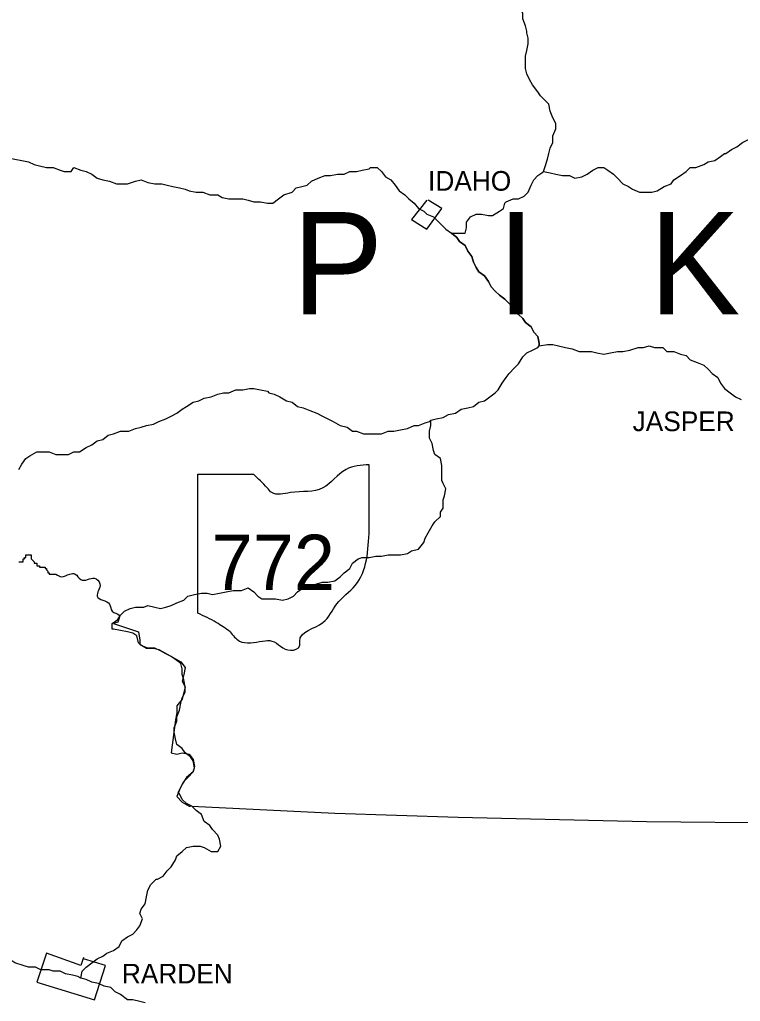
# Model space of a CAD drawing. Extents: x 0 to 34, y 0 to 22.
# Drawn here: x 5.134 to 5.85, y 17.302 to 18.276 of the extents above; entities that cross this region are included whole.
import ezdxf

# ---------------------------------------------------------------- set-up
doc = ezdxf.new("R2010")
doc.units = 0
doc.layers.add('Default', color=7, linetype='Continuous')
doc.layers.add('TR_Turning_Path1', color=7, linetype='Continuous')

msp = doc.modelspace()

# ---------------------------------------------------------------- linework, layer by layer
at = {"layer": 'Default'}
msp.add_line((5.23183, 17.67809), (5.22774, 17.67673), dxfattribs=at)
for points in [[(5.63813, 18.26437), (5.63677, 18.26982), (5.63404, 18.27664), (5.63404, 18.28209), (5.63132, 18.28891), (5.62995, 18.29436), (5.62995, 18.30118), (5.62723, 18.30663), (5.62586, 18.31345), (5.62586, 18.3189), (5.62314, 18.32572), (5.62177, 18.33254), (5.62041, 18.33935), (5.62041, 18.34344), (5.62041, 18.35026), (5.62041, 18.35162)], [(5.65449, 18.1253), (5.65586, 18.12939), (5.65858, 18.13757), (5.65995, 18.14302), (5.66131, 18.14848), (5.66404, 18.15393), (5.66404, 18.16075), (5.66677, 18.16756), (5.66677, 18.17302), (5.66404, 18.17847), (5.66131, 18.18529), (5.65995, 18.1921), (5.65586, 18.19619), (5.65177, 18.20029), (5.64904, 18.20438), (5.64359, 18.21119), (5.64086, 18.21665), (5.63813, 18.2221), (5.63677, 18.22755), (5.63677, 18.23301), (5.63677, 18.23982), (5.63813, 18.24528), (5.6395, 18.25209), (5.6395, 18.25755), (5.63813, 18.263), (5.63813, 18.263), (5.63813, 18.26437)], [(5.83583, 18.14302), (5.84128, 18.14711), (5.84674, 18.14984), (5.85219, 18.15393), (5.85764, 18.15666), (5.8631, 18.15802), (5.86991, 18.15802), (5.87537, 18.15802), (5.88082, 18.15529), (5.88764, 18.15393), (5.89309, 18.15529), (5.89582, 18.15666)], [(5.65449, 18.1253), (5.66131, 18.12393), (5.66677, 18.12257), (5.67358, 18.12121), (5.6804, 18.12121), (5.68585, 18.11848), (5.69267, 18.11984), (5.69812, 18.12257), (5.70358, 18.12666), (5.70903, 18.12939), (5.71448, 18.12939), (5.71858, 18.12666), (5.72403, 18.12257), (5.72812, 18.11848), (5.73357, 18.11303), (5.73903, 18.1103), (5.74312, 18.10757), (5.74993, 18.10485), (5.75675, 18.10485), (5.7622, 18.10485), (5.76766, 18.10621), (5.77448, 18.1103), (5.78129, 18.11303), (5.78402, 18.11712), (5.79084, 18.12121), (5.79629, 18.1253), (5.80038, 18.12939), (5.80583, 18.12939), (5.81401, 18.13211), (5.8181, 18.13484), (5.82492, 18.1362), (5.83038, 18.14029), (5.83447, 18.14302), (5.83583, 18.14302), (5.83583, 18.14302)], [(5.0655, 18.10212), (5.07231, 18.10212), (5.0764, 18.10621), (5.08049, 18.1103), (5.08731, 18.11303), (5.0914, 18.11848), (5.09686, 18.12257), (5.10231, 18.12666), (5.1064, 18.13075), (5.11049, 18.13484), (5.11731, 18.13757), (5.12276, 18.13893), (5.12958, 18.13757), (5.13639, 18.1362), (5.14321, 18.13484), (5.14867, 18.13211), (5.15412, 18.13075), (5.16094, 18.12939), (5.16775, 18.12939), (5.17457, 18.12666), (5.17866, 18.1253), (5.18548, 18.1253), (5.18548, 18.1253)], [(5.18548, 18.1253), (5.1882, 18.12939), (5.19502, 18.12666), (5.20048, 18.1253), (5.20593, 18.12257), (5.21138, 18.11848), (5.21684, 18.11712), (5.22365, 18.11575), (5.23047, 18.11303), (5.23592, 18.11303), (5.24138, 18.11303), (5.24956, 18.11575), (5.25501, 18.11712), (5.26183, 18.11439), (5.26865, 18.11303), (5.27546, 18.11303), (5.28092, 18.11166), (5.28637, 18.1103), (5.29319, 18.10894), (5.29864, 18.10757), (5.30273, 18.10621), (5.30273, 18.10621)], [(5.30273, 18.10621), (5.30955, 18.10485), (5.31637, 18.10485), (5.32318, 18.10212), (5.33136, 18.10212), (5.33545, 18.09939), (5.34227, 18.09803), (5.34909, 18.09803), (5.35591, 18.09803), (5.36136, 18.09667), (5.36681, 18.0953), (5.37363, 18.0953), (5.38045, 18.09394), (5.3859, 18.09394), (5.39135, 18.09803), (5.39681, 18.10212), (5.40499, 18.10485), (5.40908, 18.10894), (5.41453, 18.1103), (5.41999, 18.11166), (5.42408, 18.11575), (5.43089, 18.11848), (5.43771, 18.12121), (5.44316, 18.12121), (5.44998, 18.12257), (5.4568, 18.12257), (5.46225, 18.1253), (5.46907, 18.1253), (5.47452, 18.12666), (5.48134, 18.12802), (5.4827, 18.12939)], [(5.4827, 18.12939), (5.48952, 18.12939), (5.49361, 18.1253), (5.4977, 18.11984), (5.50315, 18.11712), (5.50724, 18.11166), (5.51134, 18.10621), (5.51679, 18.10212), (5.52088, 18.09803), (5.52633, 18.09394), (5.53042, 18.08848), (5.53588, 18.08576), (5.5386, 18.08303), (5.54542, 18.0803), (5.54815, 18.07758), (5.5536, 18.07212), (5.55769, 18.06803), (5.56315, 18.06394), (5.56315, 18.06394), (5.56315, 18.06394)], [(5.61768, 18.0953), (5.6245, 18.09803), (5.62995, 18.09803), (5.63541, 18.10076), (5.6395, 18.10485), (5.64222, 18.11166), (5.64495, 18.11712), (5.64904, 18.12121), (5.65313, 18.12393), (5.65449, 18.1253)], [(5.5386, 18.09667), (5.52361, 18.07758), (5.5386, 18.06803), (5.5536, 18.08848), (5.53997, 18.09667)], [(5.56315, 18.06394), (5.56996, 18.06394), (5.57678, 18.06394), (5.57814, 18.0694), (5.57814, 18.07485), (5.58223, 18.0803), (5.58769, 18.08303), (5.59314, 18.08303), (5.59996, 18.08167), (5.60405, 18.08167), (5.61086, 18.08576), (5.61496, 18.08848), (5.61632, 18.09394), (5.61632, 18.09394), (5.61768, 18.0953)], [(5.6504, 17.95214), (5.6504, 17.95351), (5.6504, 17.95487), (5.64904, 17.96169), (5.64495, 17.96578), (5.64222, 17.97123), (5.63677, 17.97532), (5.63404, 17.97941), (5.62995, 17.9835), (5.62586, 17.98895), (5.62041, 17.99441), (5.61632, 17.9985), (5.61086, 18.00259), (5.60677, 18.00668), (5.60268, 18.01077), (5.59996, 18.01622), (5.59587, 18.02168), (5.59041, 18.02577), (5.58769, 18.02986), (5.58496, 18.03531), (5.5836, 18.04076), (5.57951, 18.04622), (5.57678, 18.05167), (5.57133, 18.05576), (5.5686, 18.05985), (5.56315, 18.06394)], [(5.56315, 18.06394), (5.5686, 18.05985), (5.57133, 18.05576), (5.57678, 18.05167), (5.57951, 18.04622), (5.5836, 18.04076), (5.58496, 18.03531), (5.58769, 18.02986), (5.59041, 18.02577), (5.59587, 18.02168), (5.59996, 18.01622), (5.60268, 18.01077), (5.60677, 18.00668), (5.61086, 18.00259), (5.61632, 17.9985), (5.62041, 17.99441), (5.62586, 17.98895), (5.62995, 17.9835), (5.63404, 17.97941), (5.63677, 17.97532), (5.64222, 17.97123), (5.64495, 17.96578), (5.64904, 17.96169), (5.6504, 17.95487), (5.6504, 17.95351), (5.6504, 17.95214)], [(5.54269, 17.87852), (5.54815, 17.87988), (5.55496, 17.88124), (5.56042, 17.88397), (5.56724, 17.88533), (5.57269, 17.88943), (5.57951, 17.89079), (5.58496, 17.89215), (5.59041, 17.89624), (5.59587, 17.89761), (5.60132, 17.9017), (5.60677, 17.90579), (5.6095, 17.90851), (5.61359, 17.91533), (5.61768, 17.92078), (5.62041, 17.92487), (5.62586, 17.93033), (5.62995, 17.93442), (5.63404, 17.94124), (5.63813, 17.94533), (5.64359, 17.94805), (5.64904, 17.95078), (5.6504, 17.95214), (5.6504, 17.95214)], [(5.54269, 17.87852), (5.54815, 17.87988), (5.55496, 17.88124), (5.56042, 17.88397), (5.56724, 17.88533), (5.57269, 17.88943), (5.57951, 17.89079), (5.58496, 17.89215), (5.59041, 17.89624), (5.59587, 17.89761), (5.60132, 17.9017), (5.60677, 17.90579), (5.6095, 17.90851), (5.61359, 17.91533), (5.61768, 17.92078), (5.62041, 17.92487), (5.62586, 17.93033), (5.62995, 17.93442), (5.63404, 17.94124), (5.63813, 17.94533), (5.64359, 17.94805), (5.64904, 17.95078), (5.6504, 17.95214), (5.6504, 17.95214)], [(5.6504, 17.95214), (5.65858, 17.95351), (5.66404, 17.95351), (5.66949, 17.95214), (5.67631, 17.95078), (5.68313, 17.94942), (5.68994, 17.94669), (5.6954, 17.94669), (5.70221, 17.94669), (5.70767, 17.94533), (5.71448, 17.94396), (5.7213, 17.94533), (5.72812, 17.94669), (5.73357, 17.94669), (5.74039, 17.94805), (5.74857, 17.95078), (5.75402, 17.95078), (5.75948, 17.95214), (5.76493, 17.95078), (5.77311, 17.95078), (5.7772, 17.94669), (5.78402, 17.94669), (5.79084, 17.94396), (5.79629, 17.9426), (5.80038, 17.93851), (5.8072, 17.93578), (5.81401, 17.93305), (5.8181, 17.92896), (5.8222, 17.92487), (5.82765, 17.92078), (5.83038, 17.91533), (5.83447, 17.90988), (5.83992, 17.90579), (5.84537, 17.9017), (5.85083, 17.89897)], [(5.6504, 17.95214), (5.65858, 17.95351), (5.66404, 17.95351), (5.66949, 17.95214), (5.67631, 17.95078), (5.68313, 17.94942), (5.68994, 17.94669), (5.6954, 17.94669), (5.70221, 17.94669), (5.70767, 17.94533), (5.71448, 17.94396), (5.7213, 17.94533), (5.72812, 17.94669), (5.73357, 17.94669), (5.74039, 17.94805), (5.74857, 17.95078), (5.75402, 17.95078), (5.75948, 17.95214), (5.76493, 17.95078), (5.77311, 17.95078), (5.7772, 17.94669), (5.78402, 17.94669), (5.79084, 17.94396), (5.79629, 17.9426), (5.80038, 17.93851), (5.8072, 17.93578), (5.81401, 17.93305), (5.8181, 17.92896), (5.8222, 17.92487), (5.82765, 17.92078), (5.83038, 17.91533), (5.83447, 17.90988), (5.83992, 17.90579), (5.84537, 17.9017), (5.85083, 17.89897)], [(5.23592, 17.86761), (5.24274, 17.86761), (5.24956, 17.87034), (5.25501, 17.8717), (5.26047, 17.87306), (5.26728, 17.87443), (5.27274, 17.87715), (5.27955, 17.87988), (5.28501, 17.88261), (5.29046, 17.88533), (5.29591, 17.88943), (5.3, 17.89215), (5.30682, 17.89624), (5.31228, 17.89761), (5.31773, 17.90033), (5.32455, 17.9017), (5.33136, 17.90442), (5.33682, 17.90579), (5.34227, 17.90579), (5.34909, 17.90851), (5.35591, 17.90851), (5.36272, 17.90988), (5.36681, 17.90988), (5.37363, 17.90851), (5.38045, 17.90715), (5.38181, 17.90579), (5.38181, 17.90579)], [(5.38181, 17.90579), (5.38726, 17.90442), (5.39272, 17.9017), (5.39953, 17.89761), (5.40499, 17.89624), (5.41044, 17.89215), (5.4159, 17.89079), (5.42271, 17.88806), (5.42953, 17.88533), (5.43498, 17.88261), (5.44044, 17.87988), (5.44589, 17.87715), (5.45271, 17.87306), (5.45953, 17.8717), (5.46498, 17.86761), (5.46907, 17.86761), (5.47589, 17.86488), (5.48134, 17.86488), (5.48816, 17.86488), (5.49361, 17.86488), (5.50043, 17.86761), (5.50588, 17.86761), (5.5127, 17.86897), (5.51952, 17.87034), (5.52633, 17.87306), (5.53042, 17.87306), (5.53724, 17.87579), (5.54133, 17.87715), (5.54269, 17.87852)], [(5.55224, 17.78717), (5.55496, 17.79126), (5.55496, 17.79944), (5.55633, 17.80353), (5.55769, 17.81035), (5.55496, 17.8158), (5.5536, 17.81853), (5.5536, 17.82671), (5.5536, 17.83352), (5.55224, 17.84034), (5.54678, 17.84443), (5.54542, 17.84852), (5.54406, 17.85534), (5.54133, 17.86079), (5.54133, 17.86761), (5.54269, 17.87306), (5.54269, 17.87715), (5.54269, 17.87852)], [(5.13367, 17.82943), (5.13639, 17.83489), (5.14048, 17.84034), (5.14458, 17.84307), (5.15139, 17.84716), (5.15685, 17.84716), (5.16366, 17.84716), (5.17048, 17.84443), (5.17593, 17.84443), (5.18275, 17.84443), (5.1882, 17.84716), (5.19366, 17.84716), (5.20048, 17.85125), (5.20593, 17.85398), (5.21138, 17.85807), (5.21684, 17.85943), (5.22229, 17.86352), (5.22774, 17.86488), (5.23456, 17.86761), (5.23592, 17.86761), (5.23592, 17.86761)], [(5.48151, 17.76978), (5.48151, 17.83421)], [(5.31125, 17.68696), (5.31125, 17.825), (5.36647, 17.825)], [(5.49361, 17.74354), (5.50043, 17.7449), (5.50588, 17.7449), (5.5127, 17.7449), (5.51952, 17.74627), (5.52361, 17.74899), (5.53042, 17.75036), (5.53588, 17.75717), (5.53724, 17.76126), (5.53997, 17.76672), (5.54406, 17.77353), (5.54678, 17.77762), (5.55224, 17.78308), (5.55224, 17.78581), (5.55224, 17.78717)], [(5.13367, 17.73809), (5.13503, 17.73809), (5.13503, 17.73809), (5.13503, 17.73809), (5.13503, 17.73809), (5.13503, 17.73809), (5.13639, 17.73809), (5.13639, 17.73809), (5.13639, 17.73809), (5.13639, 17.73809), (5.13776, 17.73809), (5.13776, 17.73809), (5.13776, 17.73809), (5.13776, 17.73809), (5.13776, 17.73809), (5.13776, 17.73809), (5.13776, 17.73809), (5.13776, 17.73809), (5.13776, 17.73809), (5.13776, 17.73945), (5.13776, 17.74081), (5.13912, 17.74081), (5.13912, 17.74081), (5.13912, 17.74081), (5.13912, 17.74218), (5.14048, 17.74218), (5.14048, 17.74218), (5.14048, 17.74218), (5.14048, 17.74218), (5.14048, 17.74218), (5.14048, 17.74218), (5.14048, 17.74354), (5.14048, 17.74354), (5.14048, 17.74354), (5.14048, 17.74354), (5.14048, 17.74354), (5.14048, 17.74354), (5.14048, 17.74354), (5.14048, 17.7449), (5.14048, 17.7449), (5.14185, 17.7449), (5.14185, 17.7449), (5.14185, 17.7449), (5.14185, 17.7449), (5.14185, 17.7449), (5.14321, 17.7449), (5.14321, 17.7449), (5.14321, 17.7449), (5.14321, 17.7449), (5.14321, 17.7449), (5.14321, 17.7449), (5.14321, 17.7449), (5.14321, 17.7449), (5.14321, 17.7449)], [(5.14321, 17.7449), (5.14321, 17.7449), (5.14321, 17.7449), (5.14458, 17.7449), (5.14458, 17.7449), (5.14458, 17.7449), (5.14594, 17.7449), (5.14594, 17.7449), (5.14594, 17.74354), (5.14594, 17.74354), (5.14594, 17.74354), (5.14594, 17.74354), (5.14594, 17.74354), (5.14594, 17.74218), (5.14594, 17.74218), (5.14594, 17.74218), (5.14594, 17.74218), (5.14594, 17.74218), (5.14594, 17.74218), (5.14594, 17.74218), (5.14594, 17.74081), (5.14594, 17.74081), (5.14594, 17.74081), (5.14594, 17.74081), (5.14594, 17.74081), (5.1473, 17.73945), (5.1473, 17.73945), (5.14867, 17.73809), (5.14867, 17.73809), (5.14867, 17.73809), (5.14867, 17.73809), (5.14867, 17.73809), (5.14867, 17.73809), (5.14867, 17.73672), (5.14867, 17.73672), (5.14867, 17.73672), (5.14867, 17.73672), (5.15003, 17.73672), (5.15003, 17.73672), (5.15139, 17.73672), (5.15139, 17.73672), (5.15139, 17.73672), (5.15139, 17.73672), (5.15139, 17.73672), (5.15139, 17.73536), (5.15139, 17.73536), (5.15139, 17.734), (5.15276, 17.734), (5.15276, 17.734), (5.15276, 17.734), (5.15276, 17.734), (5.15412, 17.734), (5.15412, 17.734), (5.15412, 17.73263), (5.15412, 17.73263), (5.15548, 17.73263), (5.15548, 17.73263), (5.15548, 17.73263), (5.15548, 17.73263), (5.15685, 17.73263), (5.15685, 17.73263), (5.15821, 17.73263), (5.15821, 17.73263), (5.15821, 17.73263), (5.15821, 17.73263), (5.15957, 17.73263), (5.15957, 17.73263), (5.15957, 17.73263), (5.15957, 17.73263), (5.15957, 17.73263), (5.15957, 17.73127), (5.15957, 17.73127), (5.16094, 17.73127), (5.16094, 17.73127), (5.16094, 17.7299), (5.16094, 17.7299), (5.16094, 17.7299), (5.16094, 17.7299), (5.16094, 17.7299), (5.16094, 17.7299), (5.16094, 17.7299), (5.16094, 17.7299), (5.1623, 17.72854), (5.1623, 17.72854), (5.1623, 17.72854), (5.1623, 17.72854), (5.1623, 17.72854), (5.1623, 17.72718), (5.16366, 17.72718), (5.16366, 17.72581), (5.16503, 17.72581), (5.16503, 17.72581), (5.16503, 17.72581), (5.16503, 17.72581), (5.16503, 17.72581), (5.16503, 17.72581), (5.16503, 17.72581), (5.16503, 17.72581), (5.16639, 17.72581), (5.16775, 17.72581), (5.16775, 17.72581)], [(5.35454, 17.70945), (5.36136, 17.71218), (5.36681, 17.70809), (5.3709, 17.704), (5.37499, 17.70127), (5.38181, 17.70127), (5.38863, 17.70127), (5.39544, 17.69991), (5.4009, 17.70127), (5.40635, 17.704), (5.41044, 17.70809), (5.4159, 17.71218), (5.42271, 17.71354), (5.42953, 17.71627), (5.43498, 17.71763), (5.44044, 17.71763), (5.44725, 17.719), (5.45271, 17.72309), (5.4568, 17.72718), (5.46225, 17.73127), (5.46498, 17.73672), (5.47043, 17.74081), (5.47452, 17.74218), (5.48134, 17.74218), (5.48816, 17.74354), (5.49225, 17.74354), (5.49361, 17.74354)], [(5.16775, 17.72581), (5.16775, 17.72581), (5.16775, 17.72581), (5.16775, 17.72581), (5.16775, 17.72581), (5.16775, 17.72581), (5.16912, 17.72581), (5.16912, 17.72581), (5.16912, 17.72581), (5.16912, 17.72581), (5.16912, 17.72581), (5.16912, 17.72581), (5.16912, 17.72581), (5.17048, 17.72581), (5.17048, 17.72581), (5.17048, 17.72581), (5.17048, 17.72581)], [(5.23456, 17.68491), (5.23865, 17.689), (5.2441, 17.69173), (5.24956, 17.69309), (5.25774, 17.69309), (5.26183, 17.69446), (5.26865, 17.69309), (5.2741, 17.69173), (5.27955, 17.69309), (5.28501, 17.69446), (5.29046, 17.69718), (5.29728, 17.69991), (5.30137, 17.704), (5.30819, 17.70536), (5.315, 17.70673), (5.32046, 17.70673), (5.32591, 17.70536), (5.33273, 17.70673), (5.33954, 17.70809), (5.34636, 17.70945), (5.35318, 17.70945), (5.35454, 17.70945)], [(5.22638, 17.67128), (5.22638, 17.67673), (5.23183, 17.68082), (5.23456, 17.68491)], [(5.22774, 17.67673), (5.25229, 17.66855), (5.25365, 17.66037), (5.25365, 17.65628), (5.26047, 17.65219), (5.26728, 17.65219), (5.27274, 17.65083), (5.29455, 17.63856), (5.29864, 17.6331), (5.29728, 17.62628), (5.29591, 17.61947), (5.29864, 17.61401), (5.29591, 17.60174), (5.29046, 17.59493), (5.29046, 17.58811), (5.2891, 17.58129), (5.28501, 17.54857), (5.29046, 17.54721), (5.29591, 17.54857), (5.30273, 17.54721), (5.30682, 17.54175), (5.30819, 17.53494), (5.30682, 17.52948), (5.3, 17.52403), (5.29591, 17.51721), (5.29319, 17.51176), (5.29046, 17.50494), (5.29591, 17.49949), (5.30273, 17.4954), (5.3041, 17.4954)], [(5.29046, 17.58402), (5.29319, 17.59084), (5.29455, 17.59765), (5.29591, 17.60311), (5.29864, 17.60856), (5.29864, 17.61401), (5.29728, 17.62083), (5.29591, 17.62628), (5.29591, 17.63174), (5.29455, 17.63719), (5.29046, 17.63992), (5.28501, 17.64401), (5.27955, 17.64674), (5.2741, 17.64946), (5.26865, 17.65219), (5.26183, 17.65219), (5.25501, 17.65492), (5.25229, 17.65764), (5.25092, 17.66446), (5.24683, 17.66719), (5.24138, 17.66855), (5.23456, 17.66991), (5.22774, 17.67128), (5.22638, 17.67128), (5.22638, 17.67128)], [(5.29182, 17.50903), (5.29455, 17.51448), (5.29728, 17.51994), (5.30137, 17.52403), (5.30682, 17.52948), (5.30819, 17.53357), (5.30682, 17.54039), (5.3041, 17.54448), (5.29864, 17.54857), (5.29591, 17.55266), (5.29046, 17.55675), (5.2891, 17.5622), (5.28773, 17.56902), (5.28773, 17.57311), (5.29046, 17.57993), (5.29046, 17.58402), (5.29046, 17.58402)], [(5.27137, 17.42314), (5.27683, 17.42586), (5.28092, 17.43132), (5.28501, 17.43541), (5.2891, 17.44222), (5.29046, 17.44631), (5.29591, 17.4504), (5.3, 17.45449), (5.30682, 17.45586), (5.31364, 17.45586), (5.31773, 17.45449), (5.32455, 17.4504), (5.33136, 17.4504), (5.33409, 17.45586), (5.33273, 17.46267), (5.33136, 17.46676), (5.32591, 17.47222), (5.32318, 17.47631), (5.31773, 17.4804), (5.315, 17.48722), (5.30955, 17.49131), (5.30546, 17.4954), (5.3, 17.49812), (5.29591, 17.50221), (5.29319, 17.50767), (5.29319, 17.50767), (5.29182, 17.50903)], [(5.30546, 17.4954), (5.44725, 17.48858), (5.56996, 17.48449), (5.75675, 17.4804), (5.89309, 17.47904), (5.96126, 17.47631), (6.15078, 17.46813), (6.42892, 17.45313), (6.53935, 17.44631), (6.69887, 17.43541), (6.73296, 17.43268)], [(5.19502, 17.32497), (5.19639, 17.33179), (5.20048, 17.33588), (5.20593, 17.33997), (5.21138, 17.34406), (5.21684, 17.34678), (5.22093, 17.34951), (5.22774, 17.35224), (5.2332, 17.35633), (5.23592, 17.36178), (5.24138, 17.36587), (5.24683, 17.3686), (5.25092, 17.37269), (5.25365, 17.37678), (5.25638, 17.3836), (5.25365, 17.38905), (5.25501, 17.39314), (5.2591, 17.39859), (5.26047, 17.40541), (5.26183, 17.41223), (5.26456, 17.41768), (5.26865, 17.42177), (5.27001, 17.42314), (5.27137, 17.42314)], [(5.19502, 17.32497), (5.19229, 17.32633), (5.18684, 17.3277), (5.18002, 17.32906), (5.17457, 17.33179), (5.16775, 17.33179), (5.16366, 17.33315), (5.15548, 17.33315), (5.15003, 17.33588), (5.14321, 17.33588), (5.13776, 17.33724), (5.12958, 17.33997), (5.12549, 17.34269), (5.1214, 17.34678), (5.11594, 17.34951), (5.11185, 17.35633), (5.1064, 17.35905), (5.09958, 17.36042)], [(5.19775, 17.34542), (5.19502, 17.33724), (5.16094, 17.34951), (5.15139, 17.32088), (5.20866, 17.30315), (5.21956, 17.33724), (5.19775, 17.34406)], [(5.2591, 17.30043), (5.25365, 17.30179), (5.24683, 17.30315), (5.24138, 17.30315), (5.23456, 17.30861), (5.22911, 17.31133), (5.22502, 17.31542), (5.2182, 17.31679), (5.21275, 17.31952), (5.20593, 17.32088), (5.20048, 17.32361), (5.19502, 17.32497)]]:
    msp.add_lwpolyline(points, dxfattribs=at)
for points in [[(5.48151, 17.83421), (5.4585, 17.8296), (5.43549, 17.8112), (5.40328, 17.8066), (5.38488, 17.8066), (5.38028, 17.8112), (5.36647, 17.825)], [(5.34346, 17.66855), (5.35267, 17.65935), (5.37567, 17.65935), (5.38488, 17.65935), (5.40328, 17.65014), (5.41249, 17.65475), (5.41249, 17.65935), (5.43549, 17.67775), (5.4493, 17.69616), (5.46771, 17.71457), (5.48151, 17.76978)], [(5.17048, 17.72581), (5.17593, 17.72309), (5.18411, 17.72581), (5.18957, 17.72581), (5.19502, 17.72036), (5.20184, 17.72036), (5.20866, 17.72172), (5.21411, 17.71627), (5.21275, 17.70945), (5.21138, 17.704), (5.21684, 17.69991), (5.22365, 17.69582), (5.22638, 17.689), (5.2332, 17.68491), (5.23183, 17.67809)], [(5.34346, 17.66855), (5.32966, 17.67775), (5.31125, 17.68696)]]:
    msp.add_spline(points, degree=3, dxfattribs=at)

# ---------------------------------------------------------------- texts
for s, height, p in [('IDAHO', 0.019502, (5.53997, 18.10621)), ('JASPER', 0.019502, (5.74312, 17.86761)), ('772', 0.05486, (5.32506, 17.70996)), ('RARDEN', 0.019502, (5.23592, 17.31952))]:
    msp.add_text(s, height=height, dxfattribs=at).set_placement(p)
at = {"layer": 'TR_Turning_Path1'}
msp.add_text('P   I   K   E', height=0.1014887, dxfattribs=at).set_placement((5.40499, 17.9835))

doc.saveas('drawing.dxf')
